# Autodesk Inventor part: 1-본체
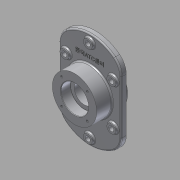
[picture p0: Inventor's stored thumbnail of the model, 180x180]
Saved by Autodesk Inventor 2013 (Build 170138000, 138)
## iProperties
Created: 2015-02
Part Number: 1-본체
Material: 알루미늄 6061
Document SubType Name: Modeling
Designer: kb543-17
Density: 1 g/cm^3
Author: kb543-17
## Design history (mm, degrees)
sketch "스케치1"
  geometry: C1 r 50 at (0, 0); 1 further point
  constraints: 1 centre point, 1 coincident
  dimensions: "d0" = 100 diameter of C1
extrude "돌출1" new body sketch "스케치1" stored distance "d2" = 70; taper "d3" = 0 deg
node "작업 평면1"
sketch "스케치5"
  geometry: L1 (-70, 60)-(-70, -60); L2 (70, 60)-(70, -60); L3 (-70, 60)-(70, 60); L4 (0, 0)-(0, 165.708); L5 (-85.236, 110)-(82.806, 110); L6 (-71.387, -110)-(86.499, -110); L7 (0, 0)-(31.667, 0); A1 r 88.979 centre (0, 21.021) between (54.875, 91.064) and (-54.875, 91.064); A2 r 39.462 centre (-30.538, 60) between (-54.875, 91.064) and (-70, 60); A3 r 39.462 centre (30.538, 60) between (70, 60) and (54.875, 91.064); A4 r 88.979 centre (0, -21.021) between (-54.875, -91.064) and (54.875, -91.064); A5 r 39.462 centre (-30.538, -60) between (-70, -60) and (-54.875, -91.064); A6 r 39.462 centre (30.538, -60) between (54.875, -91.064) and (70, -60)
  constraints: 14 end point, 12 point on circle, 6 centre point, 6 tangent, 4 equal radius, 4 parallel, 2 perpendicular, 2 point on line, 1 vertical, 1 vertical alignment
  dimensions: "d128" = 70 distance from line of L4.start L1; "d129" = 60 vertical distance of L1.start L4.start; "d130" = 120 distance of L1.start L1.end; "d131" = 70 distance from line of L2 L4.start; "d132" = 60 vertical distance of L2.start L4.start; "d133" = 120 distance of L2.start L2.end (derived); "d134" = 50 distance from line of L2.start L5; "d135" = 50 distance from line of L2.end L6; "d136" = 88.97858 radius of A1
extrude "돌출4" join sketch "스케치5" distance "d137" = 12; taper "d138" = 0 deg
hole "구멍11" diameter "d141" = 45; stored, may be unused: countersink angle "d145" = 90 deg, drill point angle "d147" = 0 deg; dims "d139" = 10, "d140" = 10, "d142" = 11, "d143" = 4, "d144" = 2, "d146" = 13
hole "구멍12" diameter "d150" = 62; stored, may be unused: countersink angle "d154" = 90 deg, drill point angle "d156" = 0 deg; dims "d148" = 10, "d149" = 10, "d151" = 11, "d152" = 4, "d153" = 2, "d155" = 22
hole "구멍13" diameter "d159" = 62; stored, may be unused: countersink angle "d163" = 90 deg, drill point angle "d165" = 0 deg; dims "d157" = 10, "d158" = 10, "d160" = 11, "d161" = 4, "d162" = 2, "d164" = 22
sketch "스케치6"
  geometry: A1 r 41 centre (0, 0) between (0, 41) and (-40.808, 3.967); 2 further points
  constraints: 3 point on circle, 1 centre point, 1 coincident, 1 vertical alignment
  dimensions: "d166" = 45 deg dimension on point (0, 0) point (-28.991, 28.991) A1.start; "d167" = 41 radius of A1
hole "구멍14" sketch "스케치6" at (-28.991, 28.991) diameter "d169" = 4.917; stored, may be unused: countersink angle "d173" = 90 deg, drill point angle "d175" = 118 deg; dims "d170" = 10, "d171" = 4, "d172" = 2, "d174" = 13
sketch "스케치7"
  geometry: L1 (-70, -60)-(-70, 60) reference; L2 (70, 60)-(70, -60) reference; L3 (-53, 60)-(-53, -60); L4 (53, -60)-(53, 60); L5 (-53, 46.5)-(53, 46.5); L6 (-105.828, -46.5)-(53, -46.5); C1 r 22.5 at (0, 0) reference; C2 r 50 at (0, 0) reference; C3 r 10 at (0, 93); C4 r 10 at (-53, 46.5); C5 r 10 at (-53, -46.5); C6 r 10 at (0, -93); C7 r 10 at (53, -46.5); C8 r 10 at (53, 46.5); A1 r 39.462 centre (30.538, -60) between (54.875, -91.064) and (70, -60) reference; A2 r 88.979 centre (0, -21.021) between (-54.875, -91.064) and (54.875, -91.064) reference; A3 r 39.462 centre (-30.538, -60) between (-70, -60) and (-54.875, -91.064) reference; A4 r 39.462 centre (-30.538, 60) between (-54.875, 91.064) and (-70, 60) reference; A5 r 88.979 centre (0, 21.021) between (54.875, 91.064) and (-54.875, 91.064) reference; A6 r 39.462 centre (30.538, 60) between (70, 60) and (54.875, 91.064) reference; A7 r 22.462 centre (-30.538, 60) between (-44.391, 77.681) and (-53, 60); A8 r 22.462 centre (-30.538, -60) between (-53, -60) and (-44.391, -77.681); A9 r 71.979 centre (0, -21.021) between (-44.391, -77.681) and (44.391, -77.681); A10 r 22.462 centre (30.538, -60) between (44.391, -77.681) and (53, -60); A11 r 22.462 centre (30.538, 60) between (53, 60) and (44.391, 77.681); A12 r 71.979 centre (0, 21.021) between (44.391, 77.681) and (-44.391, 77.681); 2 further points
  constraints: 13 point on circle, 12 centre point, 8 end point, 5 equal radius, 4 point on line, 1 coincident, 1 parallel, 1 perpendicular, 1 vertical alignment, 7 other
  dimensions: "d179" = 17 distance between parallel lines of L3 L1; "d183" = 20 diameter of C3; "d184" = 20 diameter of C4 (derived); "d185" = 17 distance from line of L1 L5.start (derived)
extrude "돌출5" join sketch "스케치7" distance "d186" = 5; taper "d187" = 0 deg
hole "구멍15" diameter "d190" = 11; stored, may be unused: countersink angle "d194" = 90 deg, drill point angle "d196" = 118 deg; dims "d188" = 10, "d189" = 10, "d191" = 11, "d192" = 4, "d193" = 2, "d195" = 13
hole "구멍16" diameter "d199" = 11; stored, may be unused: countersink angle "d203" = 90 deg, drill point angle "d205" = 118 deg; dims "d197" = 10, "d198" = 10, "d200" = 11, "d201" = 4, "d202" = 2, "d204" = 13
hole "구멍17" diameter "d208" = 11; stored, may be unused: countersink angle "d212" = 90 deg, drill point angle "d214" = 118 deg; dims "d206" = 10, "d207" = 10, "d209" = 11, "d210" = 4, "d211" = 2, "d213" = 13
hole "구멍18" diameter "d217" = 11; stored, may be unused: countersink angle "d221" = 90 deg, drill point angle "d223" = 118 deg; dims "d215" = 10, "d216" = 10, "d218" = 11, "d219" = 4, "d220" = 2, "d222" = 13
hole "구멍19" diameter "d226" = 11; stored, may be unused: countersink angle "d230" = 90 deg, drill point angle "d232" = 118 deg; dims "d224" = 10, "d225" = 10, "d227" = 11, "d228" = 4, "d229" = 2, "d231" = 13
hole "구멍20" diameter "d235" = 11; stored, may be unused: countersink angle "d239" = 90 deg, drill point angle "d241" = 118 deg; dims "d233" = 10, "d234" = 10, "d236" = 11, "d237" = 4, "d238" = 2, "d240" = 13
fillet "모깎기3" dims "d242" = 3, "d243" = 0.3
chamfer "모따기2" distance "d244" = 1; stored, may be unused: second distance "d245" = 2, angle "d246" = 45 deg
sketch "스케치8"
  geometry: 2 further points
  constraints: 1 vertical alignment, 1 other
  dimensions: "d247" = 65 distance of point (0, 65) point (0, 0)
feature "엠보싱1" sketch "스케치8" dims "d25" = 2, "d248" = 1, "d249" = 0
sketch "스케치2"
  geometry: L1 (-70, 60)-(-70, -60); L2 (70, -60)-(70, 60); L3 (-70, 60)-(70, 60); L4 (70, -60)-(-70, -60); L5 (0, 0)-(31.591, 0); L6 (-83.343, 110)-(87.56, 110); L7 (-64.354, -110)-(81.564, -110); L8 (0, 217.088)-(0, -206.065); C1 r 17 at (-53, 60); C2 r 17 at (53, 62.823)
  constraints: 20 end point, 4 parallel, 2 centre point, 2 perpendicular, 2 point on line, 2 tangent, 1 vertical
  dimensions: "d5" = 140 distance between parallel lines of L2 L1; "d7" = 70 distance from line of L2 L5.start (= 0.5 x d5); "d9" = 120 distance of L2.end L2.start; "d14" = 50 distance between parallel lines of L6 L3; "d15" = 50 distance between parallel lines of L4 L7; "d16" = 220 distance between parallel lines of L7 L6 (derived); "d126" = 34 diameter of C1; "d127" = 34 diameter of C2
extrude "돌출2" join sketch "스케치2" distance "d18" = 12; taper "d19" = 0 deg
hole "구멍1" diameter "d22" = 45; stored, may be unused: countersink angle "d26" = 90 deg, drill point angle "d28" = 118 deg; dims "d20" = 10, "d21" = 10, "d23" = 6, "d24" = 4, "d25" = 2, "d27" = 8
hole "구멍2" diameter "d31" = 62; stored, may be unused: countersink angle "d35" = 90 deg, drill point angle "d37" = 0 deg; dims "d29" = 10, "d30" = 10, "d32" = 6, "d33" = 4, "d34" = 2, "d36" = 22
hole "구멍3" diameter "d40" = 62; stored, may be unused: countersink angle "d44" = 90 deg, drill point angle "d46" = 0 deg; dims "d38" = 10, "d39" = 10, "d41" = 6, "d42" = 4, "d43" = 2, "d45" = 22
sketch "스케치3"
  geometry: A1 r 41 centre (0, 0) between (0, 41) and (-39.842, 9.674); 2 further points
  constraints: 3 point on circle, 2 vertical alignment, 1 centre point, 1 coincident
  dimensions: "d47" = 45 deg dimension on point (0, 0) point (-28.991, 28.991) A1.start; "d48" = 41 radius of A1
hole "구멍4" sketch "스케치3" at (-28.991, 28.991) diameter "d50" = 4.917; stored, may be unused: countersink angle "d54" = 90 deg, drill point angle "d56" = 118 deg; dims "d51" = 10, "d52" = 4, "d53" = 2, "d55" = 13
sketch "스케치4"
  geometry: L1 (70, -59.495)-(70, 59.495) reference; L2 (-70, 59.495)-(-70, -59.495) reference; L3 (53, -56.19)-(53, 62.799); L4 (-53, 59.495)-(-53, -59.495); L5 (-53, -53)-(53, -53); L6 (53, -53)-(53, 53); L7 (53, 53)-(-53, 53); L8 (-53, 53)-(-53, -53); L9 (-53, -53)-(53, 53); L10 (53, -53)-(-53, 53); C1 r 10 at (0, 93); C2 r 10 at (-53, 53); C3 r 10 at (53, 53); C4 r 10 at (-53, -53); C5 r 10 at (53, -53); C6 r 10 at (0, -93); A1 r 74 centre (0, 36) between (69.831, 60.487) and (-69.831, 60.487) reference; A2 r 74 centre (0, -36) between (-69.831, -60.487) and (69.831, -60.487) reference; A3 r 57 centre (0, 36) between (53.789, 54.862) and (-53.789, 54.862); A4 r 57 centre (0, -36) between (-53.789, -54.862) and (53.789, -54.862); 3 further points
  constraints: 16 end point, 8 centre point, 6 coincident, 6 point on circle, 5 equal radius, 4 parallel, 2 midpoint, 2 perpendicular, 2 vertical alignment, 1 collinear, 1 horizontal
  dimensions: "d60" = 17 distance between parallel lines of L4 L2; "d61" = 17 distance between parallel lines of L1 L3; "d62" = 17 radial gap between concentric circles of A3 A1; "d63" = 17 radial gap between concentric circles of A4 A2; "d64" = 20 diameter of C1
extrude "돌출3" join sketch "스케치4" distance "d65" = 5; taper "d66" = 0 deg
hole "구멍5" diameter "d69" = 11; stored, may be unused: countersink angle "d73" = 90 deg, drill point angle "d75" = 0 deg; dims "d67" = 10, "d68" = 10, "d70" = 11, "d71" = 4, "d72" = 2, "d74" = 13
hole "구멍6" diameter "d78" = 11; stored, may be unused: countersink angle "d82" = 90 deg, drill point angle "d84" = 0 deg; dims "d76" = 10, "d77" = 10, "d79" = 11, "d80" = 4, "d81" = 2, "d83" = 13
hole "구멍7" diameter "d87" = 11; stored, may be unused: countersink angle "d91" = 90 deg, drill point angle "d93" = 0 deg; dims "d85" = 10, "d86" = 10, "d88" = 11, "d89" = 4, "d90" = 2, "d92" = 13
hole "구멍8" diameter "d96" = 11; stored, may be unused: countersink angle "d100" = 90 deg, drill point angle "d102" = 0 deg; dims "d94" = 10, "d95" = 10, "d97" = 11, "d98" = 4, "d99" = 2, "d101" = 13
hole "구멍9" diameter "d105" = 11; stored, may be unused: countersink angle "d109" = 90 deg, drill point angle "d111" = 0 deg; dims "d103" = 10, "d104" = 10, "d106" = 11, "d107" = 4, "d108" = 2, "d110" = 13
hole "구멍10" diameter "d114" = 11; stored, may be unused: countersink angle "d118" = 90 deg, drill point angle "d120" = 0 deg; dims "d112" = 10, "d113" = 10, "d115" = 11, "d116" = 4, "d117" = 2, "d119" = 13
chamfer "모따기1" distance "d121" = 1; stored, may be unused: second distance "d122" = 2, angle "d123" = 45 deg
fillet "모깎기1" dims "d124" = 0.3
fillet "모깎기2" dims "d125" = 3
node "솔리드1"
pattern_circular "원형 패턴2" dims angle "d177" = 360 deg
mirror "대칭2"
pattern_circular "원형 패턴1" dims angle "d58" = 360 deg
mirror "대칭1"
node "절단 모서리 투영1"
other parameters: "d4" = -23
